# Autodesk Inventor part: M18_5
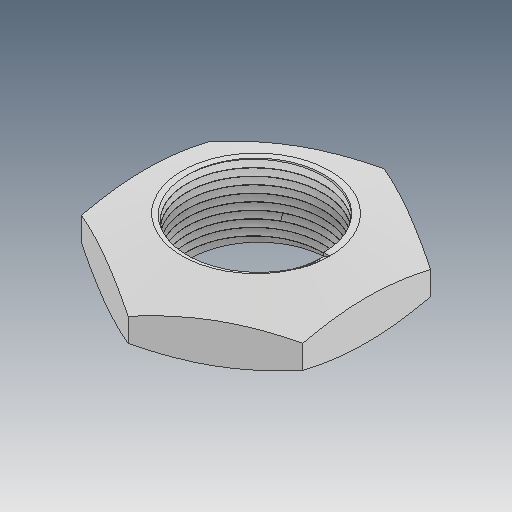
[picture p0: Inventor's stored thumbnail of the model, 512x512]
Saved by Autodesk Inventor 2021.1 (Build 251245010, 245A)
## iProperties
Created: 2019-04
Part Number: M18_5
Material: Ogólny
Document SubType Name: Modeling
Designer: user
Density: 1 g/cm^3
Appearance: Domyślna
Author: user
Revision Number: ÈÎºÎ
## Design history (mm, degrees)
feature "ÊäÈë1"
node "Bryła1"
